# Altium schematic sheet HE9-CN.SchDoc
size 840 x 594 mm; Engineer: Jack Ou; DocumentNumber: 1; Revision: 1.0; SheetNumber: 1; SheetTotal: 1
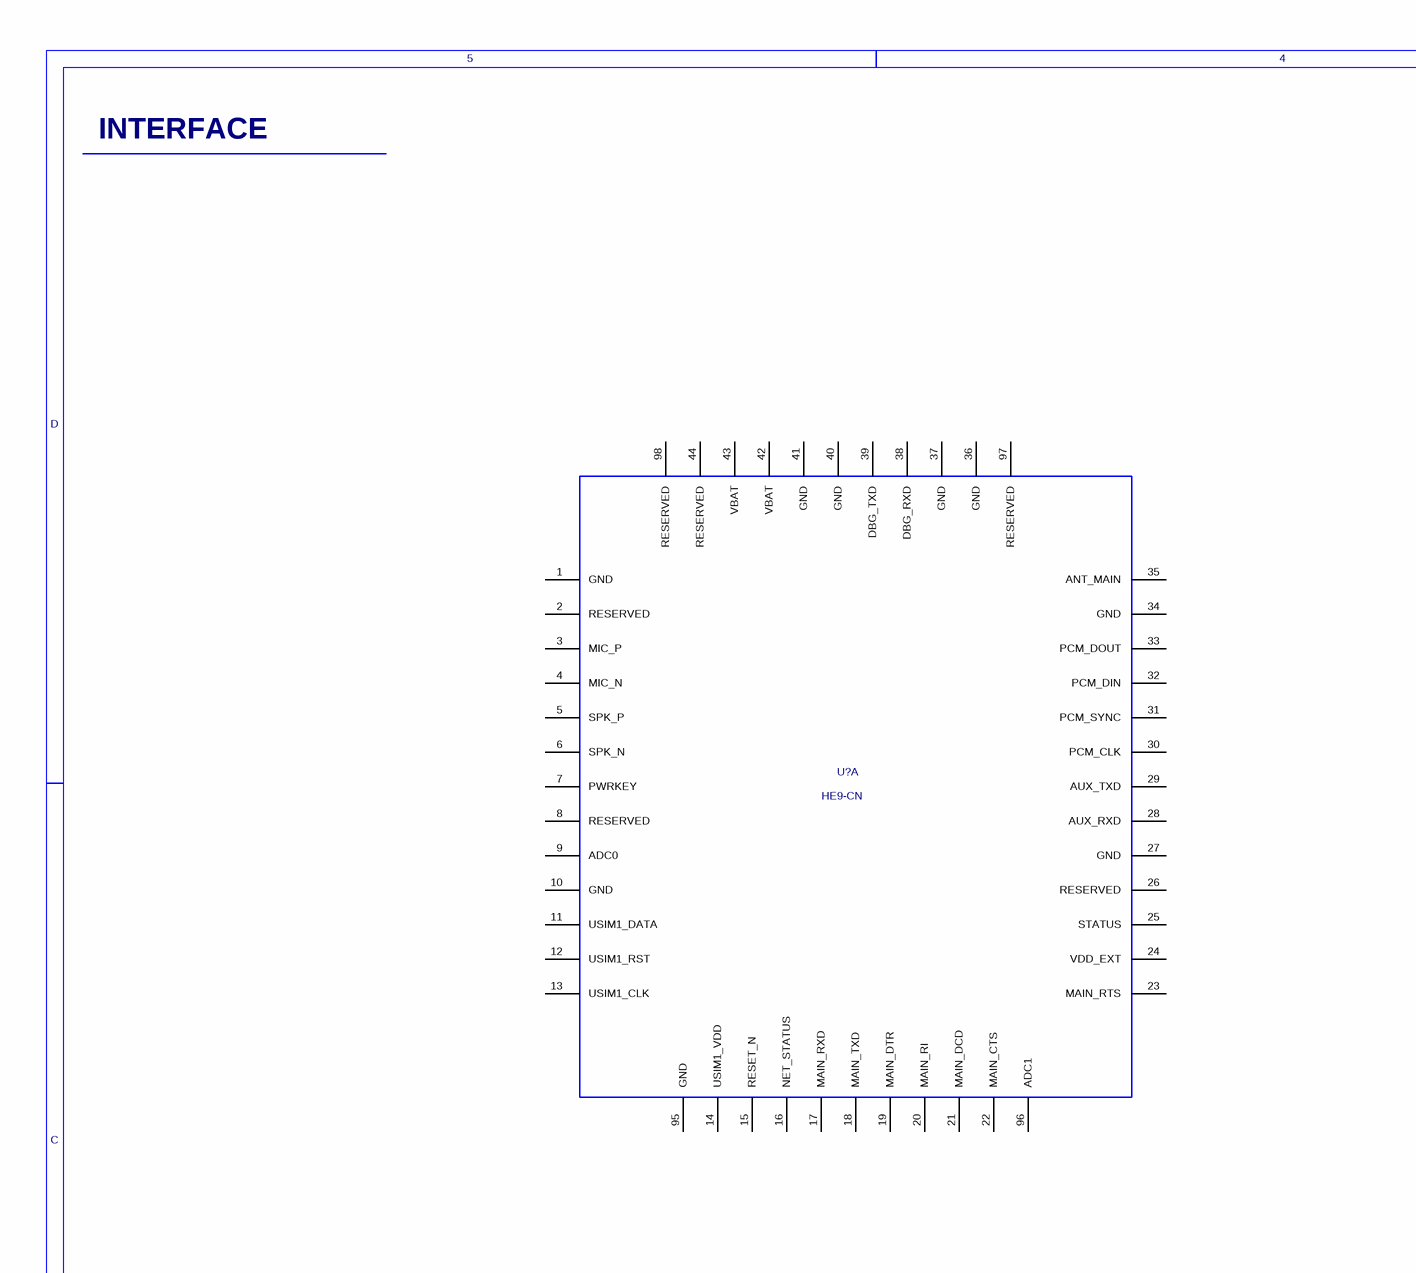
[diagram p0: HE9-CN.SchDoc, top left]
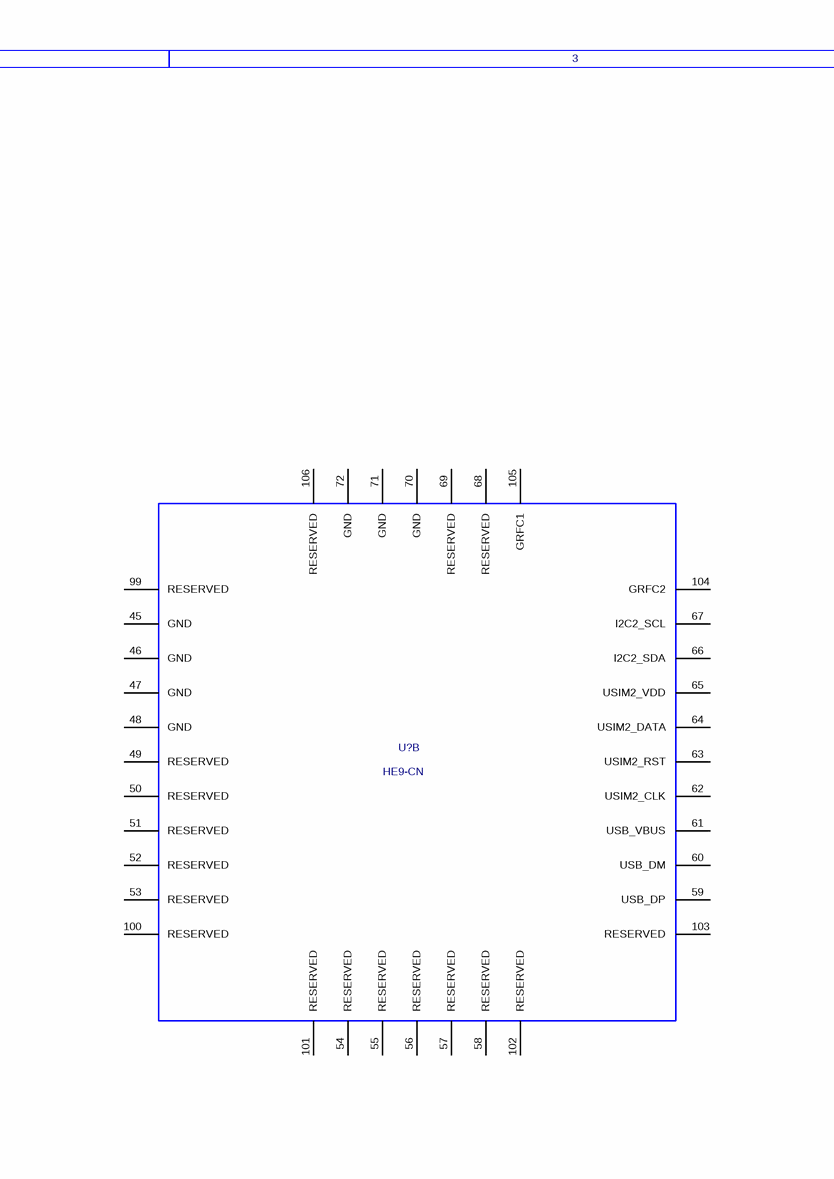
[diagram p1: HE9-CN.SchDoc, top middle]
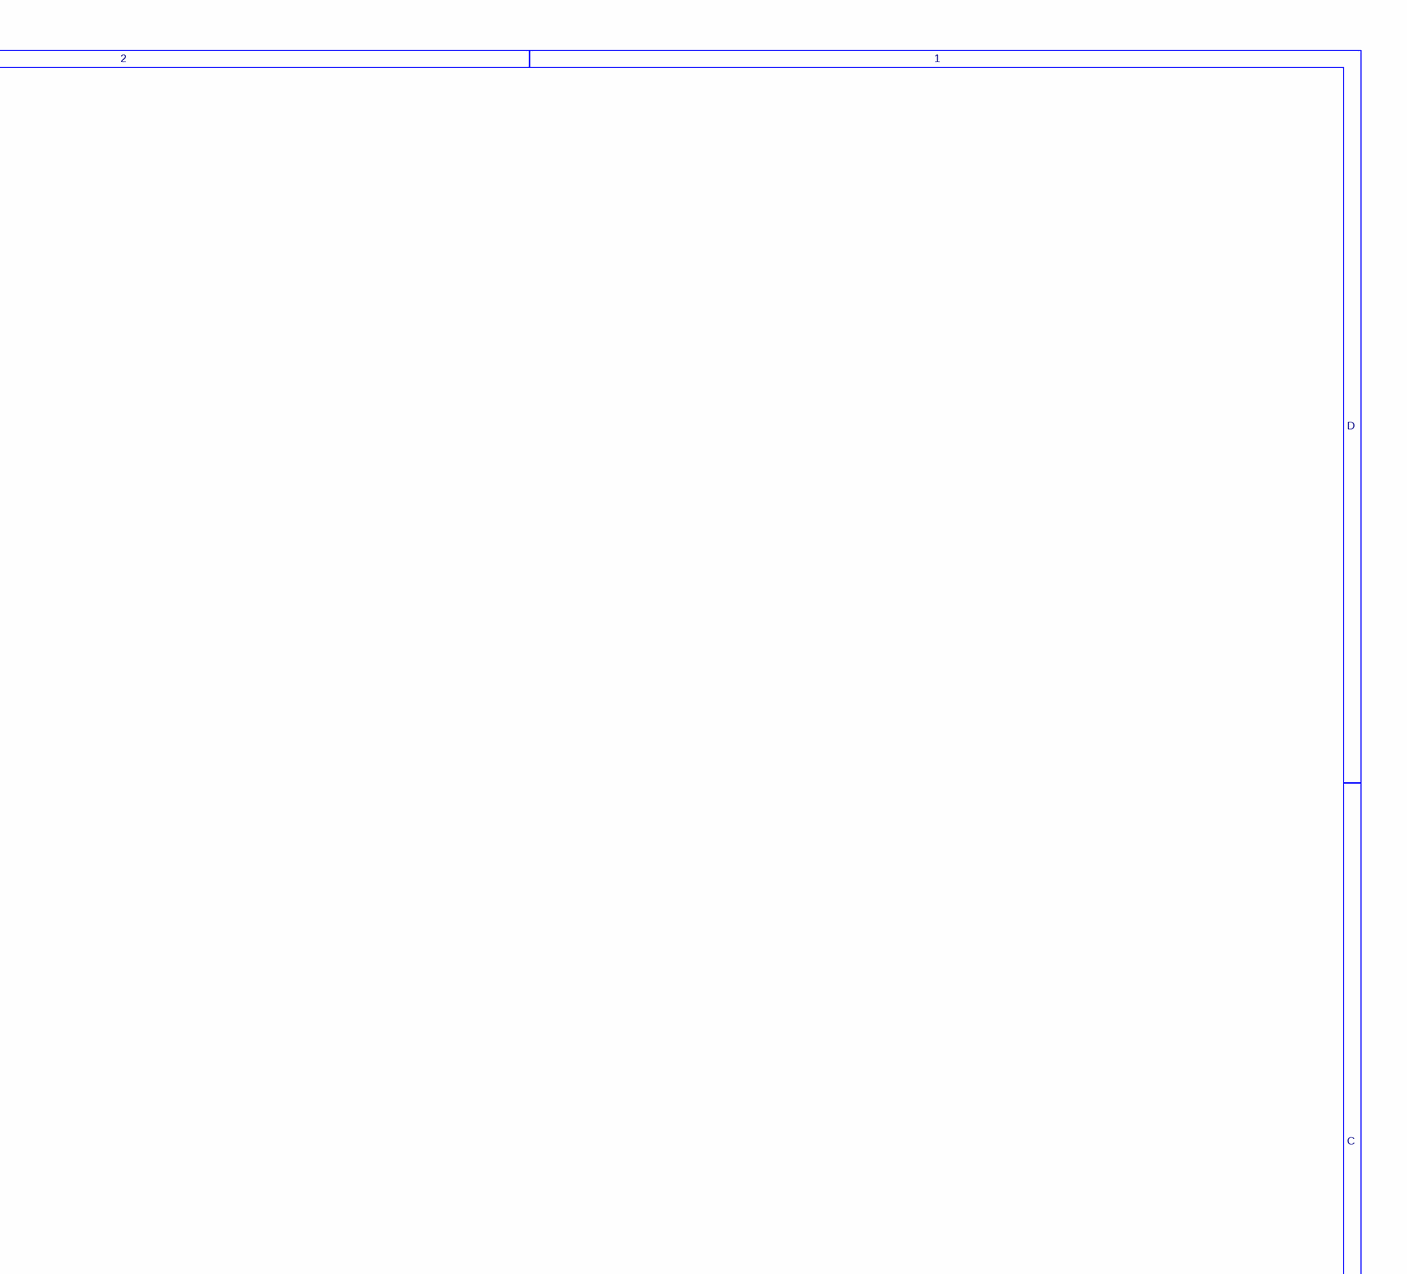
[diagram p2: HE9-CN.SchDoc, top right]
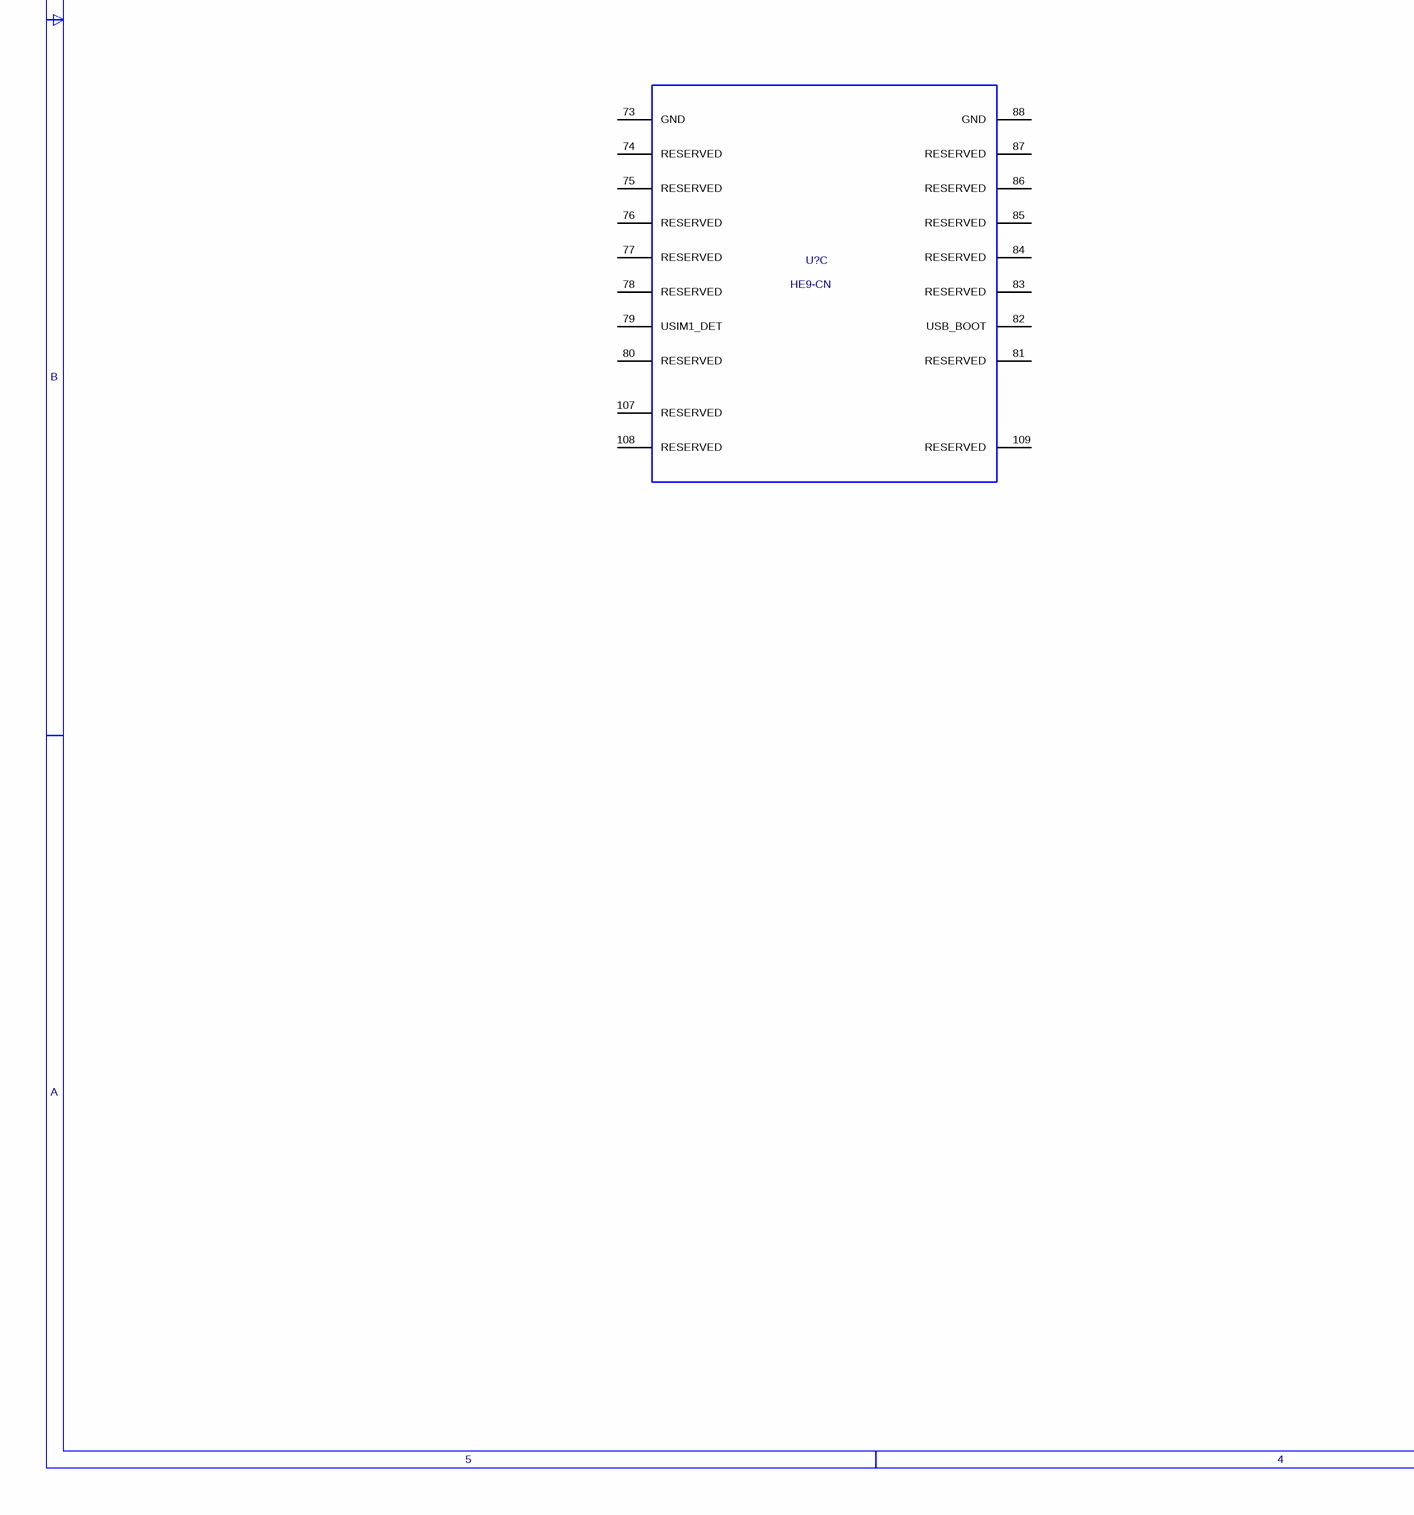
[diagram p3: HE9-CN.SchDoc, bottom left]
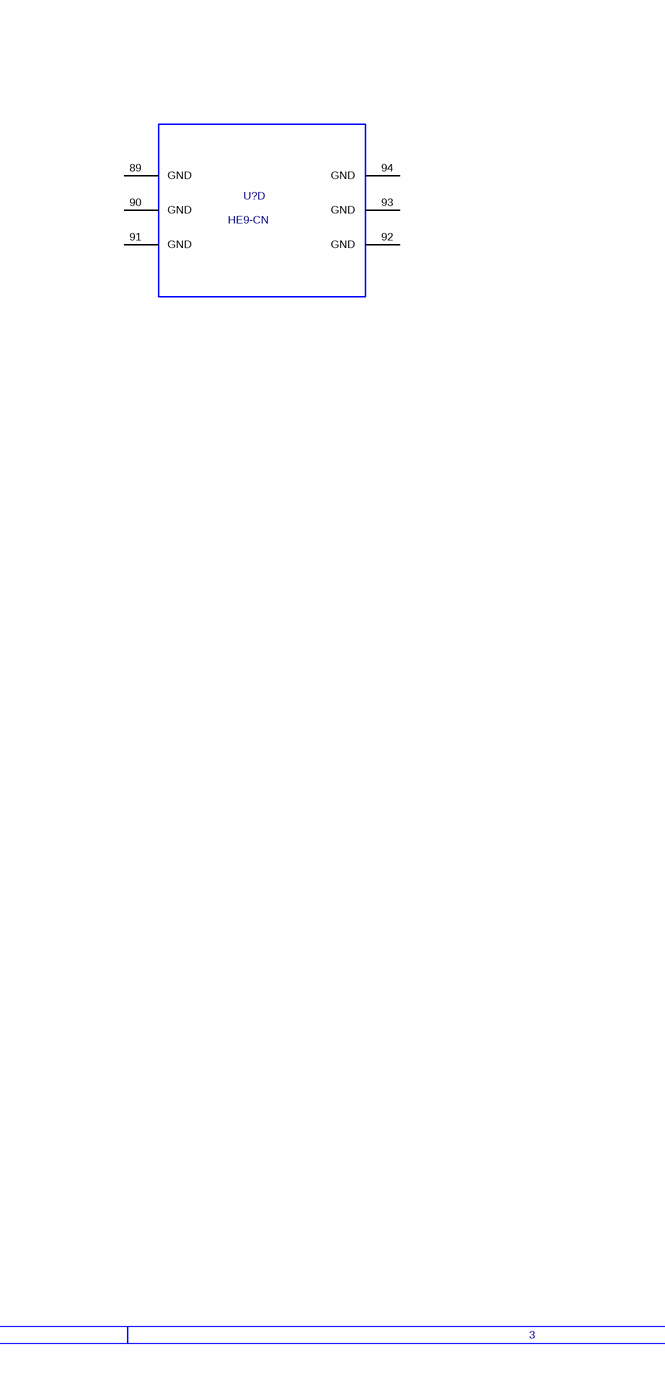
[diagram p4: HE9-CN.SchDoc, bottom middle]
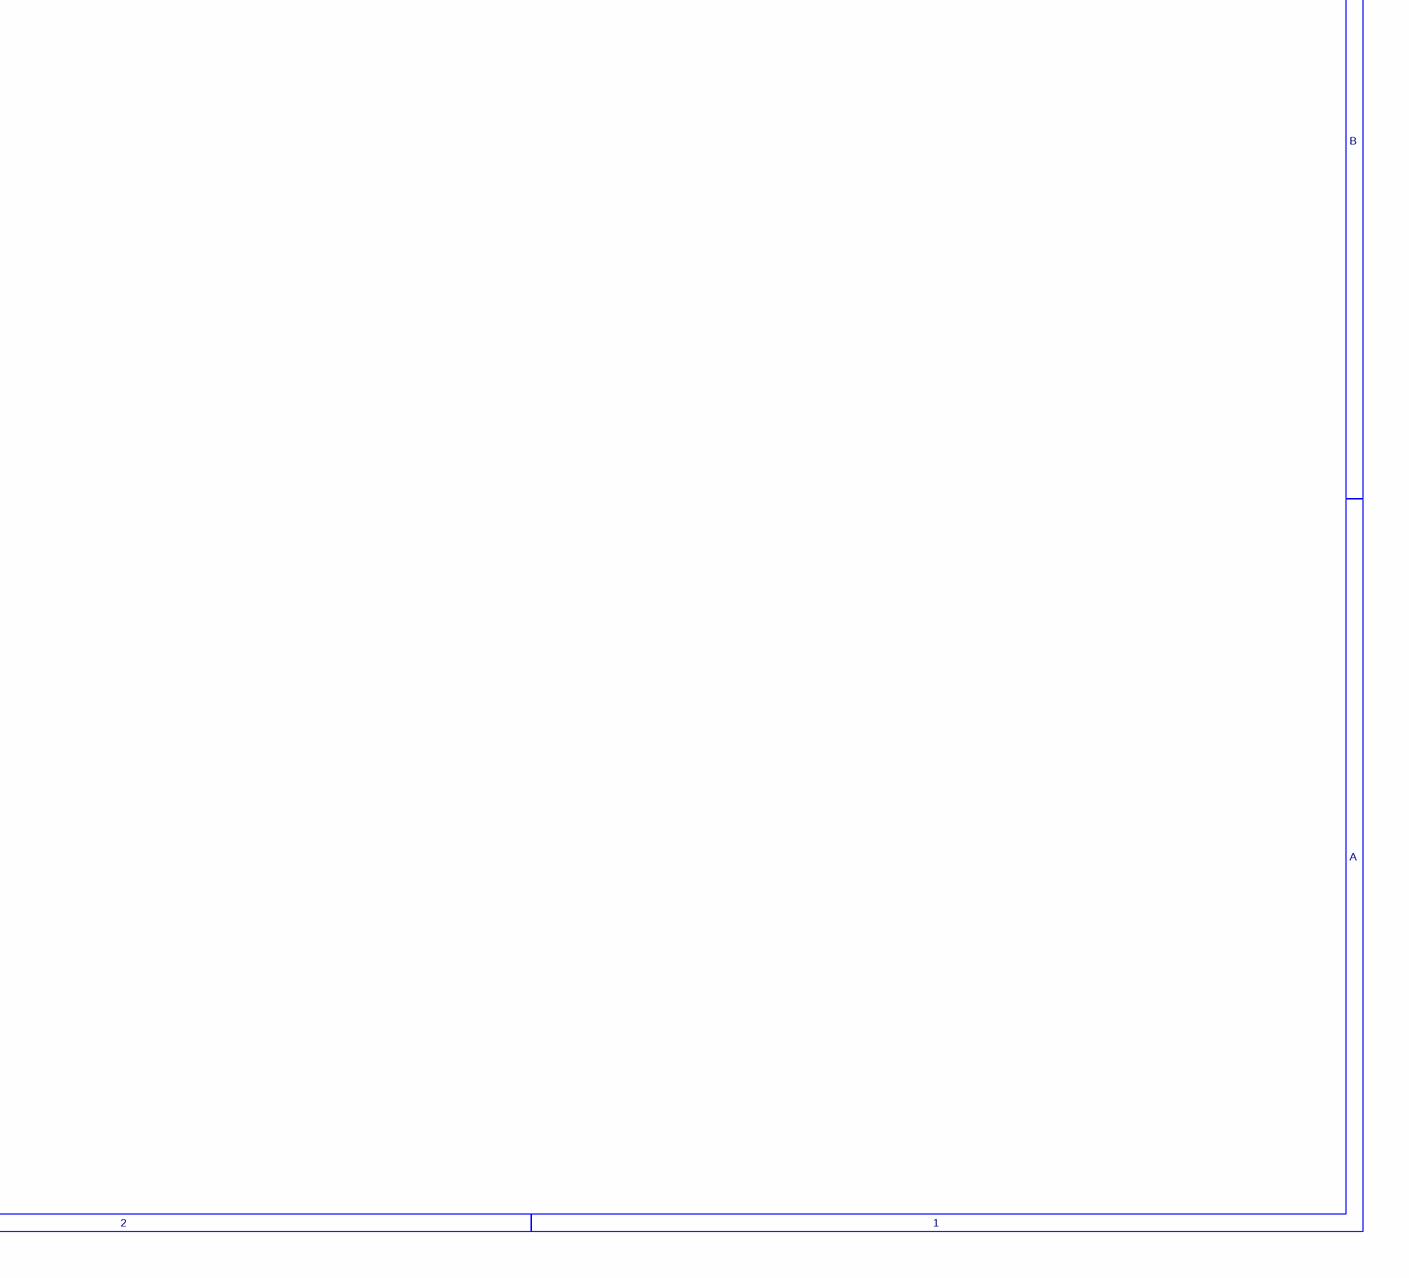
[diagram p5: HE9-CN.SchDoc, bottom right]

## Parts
(Parts that share a designator on the sheet are numbered #1, #2 ... from top to bottom, then left to right.)
U?#1  HE9-CN  [LV9-CN]  (part B of 4)
U?#2  HE9-CN  [LV9-CN]  (part A of 4)
U?#3  HE9-CN  [LV9-CN]  (part C of 4)
U?#4  HE9-CN  [LV9-CN]  (part D of 4)

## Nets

Not connected (* = marked no-connect by the designer): U?#1 45(GND) 46(GND) 47(GND) 48(GND) 49(RESERVED) 50(RESERVED) 51(RESERVED) 52(RESERVED) 53(RESERVED) 54(RESERVED) 55(RESERVED) 56(RESERVED) 57(RESERVED) 58(RESERVED) 59(USB_DP) 60(USB_DM) 61(USB_VBUS) 62(USIM2_CLK) 63(USIM2_RST) 64(USIM2_DATA) 65(USIM2_VDD) 66(I2C2_SDA) 67(I2C2_SCL) 68(RESERVED) 69(RESERVED) 70(GND) 71(GND) 72(GND) 99(RESERVED) 100(RESERVED) 101(RESERVED) 102(RESERVED) 103(RESERVED) 104(GRFC2) 105(GRFC1) 106(RESERVED); U?#2 1(GND) 2(RESERVED) 3(MIC_P) 4(MIC_N) 5(SPK_P) 6(SPK_N) 7(PWRKEY) 8(RESERVED) 9(ADC0) 10(GND) 11(USIM1_DATA) 12(USIM1_RST) 13(USIM1_CLK) 14(USIM1_VDD) 15(RESET_N) 16(NET_STATUS) 17(MAIN_RXD) 18(MAIN_TXD) 19(MAIN_DTR) 20(MAIN_RI) 21(MAIN_DCD) 22(MAIN_CTS) 23(MAIN_RTS) 24(VDD_EXT) 25(STATUS) 26(RESERVED) 27(GND) 28(AUX_RXD) 29(AUX_TXD) 30(PCM_CLK) 31(PCM_SYNC) 32(PCM_DIN) 33(PCM_DOUT) 34(GND) 35(ANT_MAIN) 36(GND) 37(GND) 38(DBG_RXD) 39(DBG_TXD) 40(GND) 41(GND) 42(VBAT) 43(VBAT) 44(RESERVED) 95(GND) 96(ADC1) 97(RESERVED) 98(RESERVED); U?#3 73(GND) 74(RESERVED) 75(RESERVED) 76(RESERVED) 77(RESERVED) 78(RESERVED) 79(USIM1_DET) 80(RESERVED) 81(RESERVED) 82(USB_BOOT) 83(RESERVED) 84(RESERVED) 85(RESERVED) 86(RESERVED) 87(RESERVED) 88(GND) 107(RESERVED) 108(RESERVED) 109(RESERVED); U?#4 89(GND) 90(GND) 91(GND) 92(GND) 93(GND) 94(GND)

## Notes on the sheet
- 5
- 4
- 3
- 2
- 1
- INTERFACE
- D
- C
- B
- A

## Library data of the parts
U?#1-U?#4 = HE9-CN: Part_Description: HE9-CN Moudle 109PIN 15.8X17.7mm H2.4mm RO; Manufacturer: Quectel; Geometry_Height: 2.4mm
